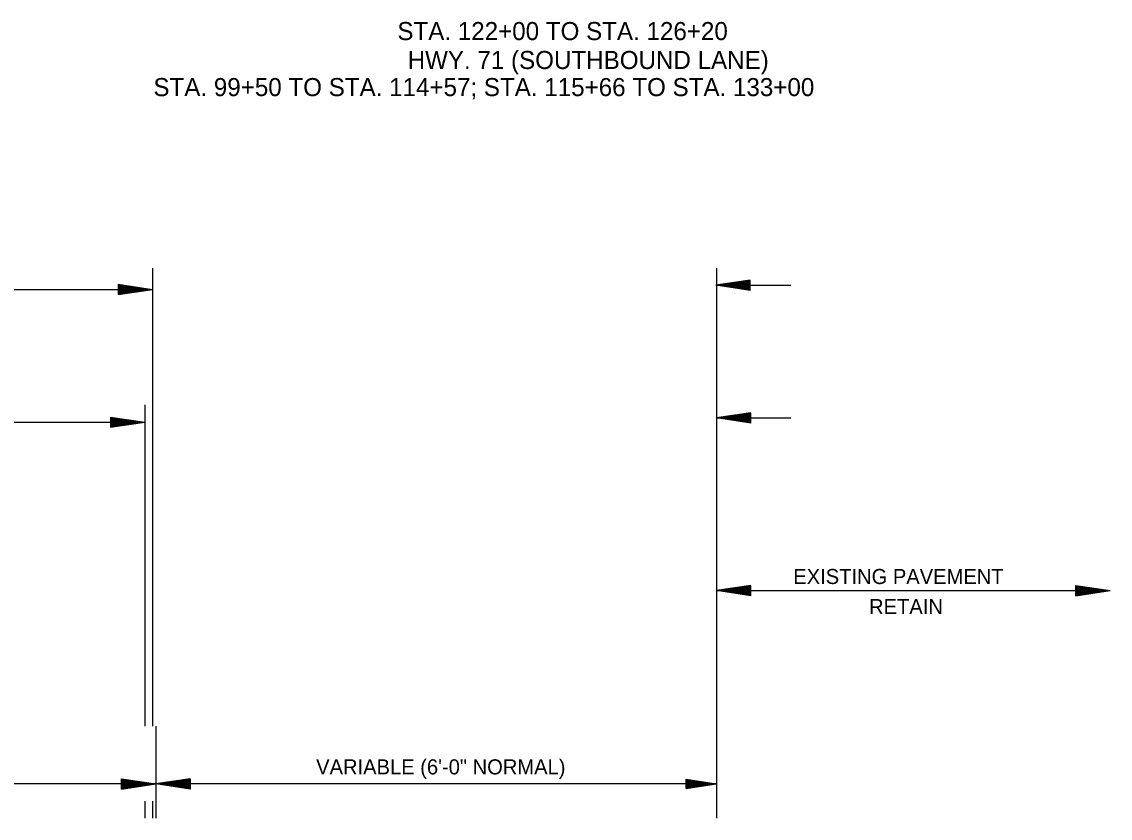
# Model space of a CAD drawing. Extents: x 634177 to 635904, y 289936 to 290970.
# Drawn here: x 635652.44 to 635695.81, y 290784.73 to 290816.46 of the extents above; entities that cross this region are included whole.
import ezdxf

# ---------------------------------------------------------------- set-up
doc = ezdxf.new("R2010")
doc.units = 0
doc.layers.add('Default', color=7, linetype='Continuous')

msp = doc.modelspace()

# ---------------------------------------------------------------- linework, layer by layer
at = {"layer": 'Default'}
for p, q in [((635657.652, 290806.648), (635657.652, 290788.394)), ((635680.116, 290806.648), (635680.116, 290784.729)), ((635656.282, 290806.001), (635657.652, 290805.797)), ((635656.282, 290806.001), (635656.282, 290805.591)), ((635656.282, 290805.968), (635657.425, 290805.797)), ((635656.282, 290805.933), (635657.188, 290805.797)), ((635656.282, 290805.9), (635656.96, 290805.797)), ((635681.467, 290806.166), (635680.099, 290805.962)), ((635681.467, 290805.756), (635680.099, 290805.962)), ((635680.099, 290805.962), (635683.084, 290805.962)), ((635681.467, 290806.133), (635680.326, 290805.962)), ((635681.467, 290805.791), (635680.326, 290805.962)), ((635681.467, 290806.098), (635680.562, 290805.962)), ((635681.467, 290805.825), (635680.562, 290805.962)), ((635681.467, 290806.065), (635680.791, 290805.962)), ((635681.467, 290805.861), (635680.791, 290805.962)), ((635681.467, 290806.026), (635681.023, 290805.962)), ((635681.467, 290805.894), (635681.023, 290805.962)), ((635681.467, 290805.995), (635681.25, 290805.962)), ((635681.467, 290805.929), (635681.25, 290805.962)), ((635681.467, 290805.756), (635681.467, 290806.166)), ((635633.875, 290805.797), (635657.652, 290805.797)), ((635656.282, 290805.861), (635656.728, 290805.797)), ((635656.282, 290805.83), (635656.501, 290805.797)), ((635656.282, 290805.591), (635657.652, 290805.797)), ((635656.282, 290805.729), (635656.728, 290805.797)), ((635656.282, 290805.66), (635657.188, 290805.797)), ((635656.282, 290805.626), (635657.425, 290805.797)), ((635656.282, 290805.696), (635656.96, 290805.797)), ((635656.282, 290805.764), (635656.501, 290805.797)), ((635657.345, 290801.194), (635657.345, 290788.394)), ((635655.975, 290800.714), (635657.345, 290800.51)), ((635655.975, 290800.714), (635655.975, 290800.304)), ((635681.484, 290800.879), (635680.116, 290800.675)), ((635681.484, 290800.846), (635680.342, 290800.675)), ((635681.484, 290800.81), (635680.577, 290800.675)), ((635681.484, 290800.778), (635680.804, 290800.675)), ((635681.484, 290800.74), (635681.037, 290800.675)), ((635681.484, 290800.707), (635681.266, 290800.675)), ((635681.484, 290800.469), (635681.484, 290800.879)), ((635635.093, 290800.51), (635657.345, 290800.51)), ((635655.975, 290800.681), (635657.114, 290800.51)), ((635655.975, 290800.645), (635656.881, 290800.51)), ((635655.975, 290800.613), (635656.653, 290800.51)), ((635655.975, 290800.575), (635656.421, 290800.51)), ((635655.975, 290800.542), (635656.192, 290800.51)), ((635655.975, 290800.304), (635657.345, 290800.51)), ((635655.975, 290800.441), (635656.421, 290800.51)), ((635655.975, 290800.373), (635656.881, 290800.51)), ((635655.975, 290800.338), (635657.114, 290800.51)), ((635655.975, 290800.407), (635656.653, 290800.51)), ((635655.975, 290800.479), (635656.192, 290800.51)), ((635680.116, 290800.675), (635683.084, 290800.675)), ((635681.484, 290800.469), (635680.116, 290800.675)), ((635681.484, 290800.503), (635680.342, 290800.675)), ((635681.484, 290800.538), (635680.577, 290800.675)), ((635681.484, 290800.572), (635680.804, 290800.675)), ((635681.484, 290800.606), (635681.037, 290800.675)), ((635681.484, 290800.644), (635681.266, 290800.675)), ((635681.486, 290794.001), (635680.116, 290793.797)), ((635680.116, 290793.797), (635695.808, 290793.797)), ((635681.486, 290793.591), (635680.116, 290793.797)), ((635681.486, 290793.968), (635680.343, 290793.797)), ((635681.486, 290793.625), (635680.343, 290793.797)), ((635681.486, 290793.932), (635680.58, 290793.797)), ((635681.486, 290793.659), (635680.58, 290793.797)), ((635681.486, 290793.899), (635680.809, 290793.797)), ((635681.486, 290793.695), (635680.809, 290793.797)), ((635681.486, 290793.862), (635681.04, 290793.797)), ((635681.486, 290793.728), (635681.04, 290793.797)), ((635681.486, 290793.829), (635681.268, 290793.797)), ((635681.486, 290793.764), (635681.268, 290793.797)), ((635681.486, 290793.591), (635681.486, 290794.001)), ((635694.44, 290794.002), (635695.808, 290793.797)), ((635694.44, 290793.591), (635694.44, 290794.002)), ((635694.44, 290793.966), (635695.581, 290793.797)), ((635694.44, 290793.932), (635695.347, 290793.797)), ((635694.44, 290793.899), (635695.12, 290793.797)), ((635694.44, 290793.862), (635694.887, 290793.797)), ((635694.44, 290793.828), (635694.657, 290793.797)), ((635694.44, 290793.591), (635695.808, 290793.797)), ((635694.44, 290793.731), (635694.887, 290793.797)), ((635694.44, 290793.659), (635695.347, 290793.797)), ((635694.44, 290793.625), (635695.581, 290793.797)), ((635694.44, 290793.694), (635695.12, 290793.797)), ((635694.44, 290793.762), (635694.657, 290793.797)), ((635657.78, 290788.394), (635657.78, 290784.729)), ((635657.78, 290786.099), (635635.348, 290786.099)), ((635656.41, 290786.303), (635657.78, 290786.099)), ((635656.41, 290785.893), (635656.41, 290786.303)), ((635656.41, 290786.27), (635657.552, 290786.099)), ((635656.41, 290786.234), (635657.317, 290786.099)), ((635656.41, 290786.201), (635657.088, 290786.099)), ((635656.41, 290786.164), (635656.857, 290786.099)), ((635656.41, 290786.131), (635656.63, 290786.099)), ((635656.41, 290785.893), (635657.78, 290786.099)), ((635656.41, 290786.03), (635656.857, 290786.099)), ((635656.41, 290785.961), (635657.317, 290786.099)), ((635656.41, 290785.927), (635657.552, 290786.099)), ((635656.41, 290785.997), (635657.088, 290786.099)), ((635656.41, 290786.066), (635656.63, 290786.099)), ((635659.148, 290786.303), (635657.78, 290786.099)), ((635680.116, 290786.099), (635657.78, 290786.099)), ((635659.148, 290785.893), (635657.78, 290786.099)), ((635659.148, 290786.27), (635658.009, 290786.099)), ((635659.148, 290785.927), (635658.009, 290786.099)), ((635659.148, 290786.234), (635658.243, 290786.099)), ((635659.148, 290785.961), (635658.243, 290786.099)), ((635659.148, 290786.201), (635658.47, 290786.099)), ((635659.148, 290785.997), (635658.47, 290786.099)), ((635659.148, 290786.164), (635658.706, 290786.099)), ((635659.148, 290786.03), (635658.706, 290786.099)), ((635659.148, 290786.131), (635658.933, 290786.099)), ((635659.148, 290786.066), (635658.933, 290786.099)), ((635659.148, 290786.303), (635659.148, 290785.893)), ((635678.916, 290786.279), (635680.116, 290786.099)), ((635678.916, 290785.919), (635678.916, 290786.279)), ((635678.916, 290786.249), (635679.916, 290786.099)), ((635678.916, 290786.218), (635679.709, 290786.099)), ((635678.916, 290786.188), (635679.509, 290786.099)), ((635678.916, 290786.158), (635679.306, 290786.099)), ((635678.916, 290786.127), (635679.106, 290786.099)), ((635678.916, 290785.919), (635680.116, 290786.099)), ((635678.916, 290786.041), (635679.306, 290786.099)), ((635678.916, 290785.98), (635679.709, 290786.099)), ((635678.916, 290785.949), (635679.916, 290786.099)), ((635678.916, 290786.01), (635679.509, 290786.099)), ((635678.916, 290786.071), (635679.106, 290786.099)), ((635657.345, 290785.415), (635657.345, 290784.729)), ((635657.652, 290785.415), (635657.652, 290784.729)), ((635657.78, 290785.415), (635657.78, 290784.729))]:
    msp.add_line(p, q, dxfattribs=at)

# ---------------------------------------------------------------- texts
for s, height, p in [('STA. 122+00 TO STA. 126+20', 0.72, (635667.405, 290815.73)), ('HWY. 71 (SOUTHBOUND LANE)', 0.72, (635667.813, 290814.579)), ('STA. 99+50 TO STA. 114+57; STA. 115+66 TO STA. 133+00', 0.72, (635657.685, 290813.498)), ('EXISTING PAVEMENT', 0.6, (635683.179, 290794.06)), ('RETAIN', 0.6, (635686.199, 290792.862)), ('VARIABLE (6\'-0" NORMAL)', 0.6, (635664.168, 290786.475))]:
    msp.add_text(s, height=height, dxfattribs=at).set_placement(p)

doc.saveas('drawing.dxf')
